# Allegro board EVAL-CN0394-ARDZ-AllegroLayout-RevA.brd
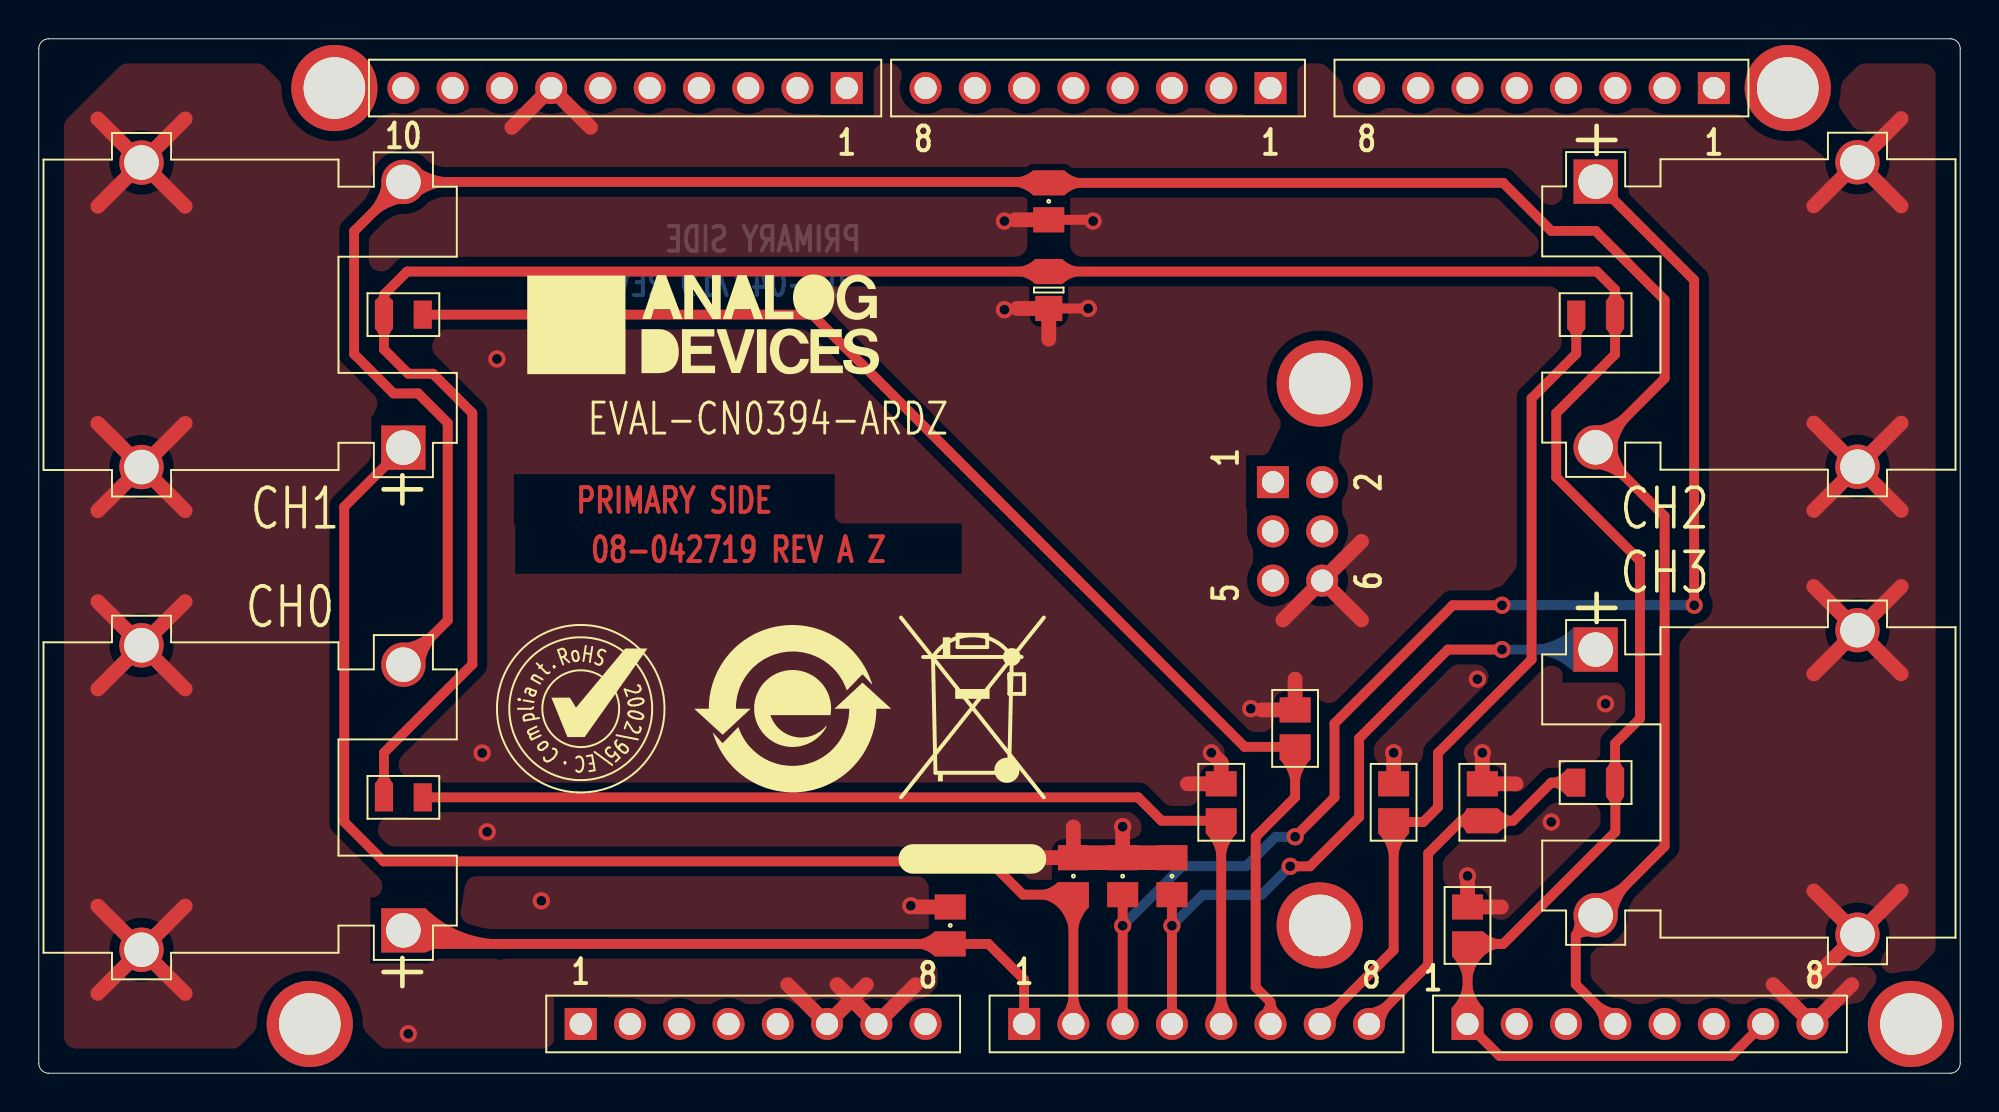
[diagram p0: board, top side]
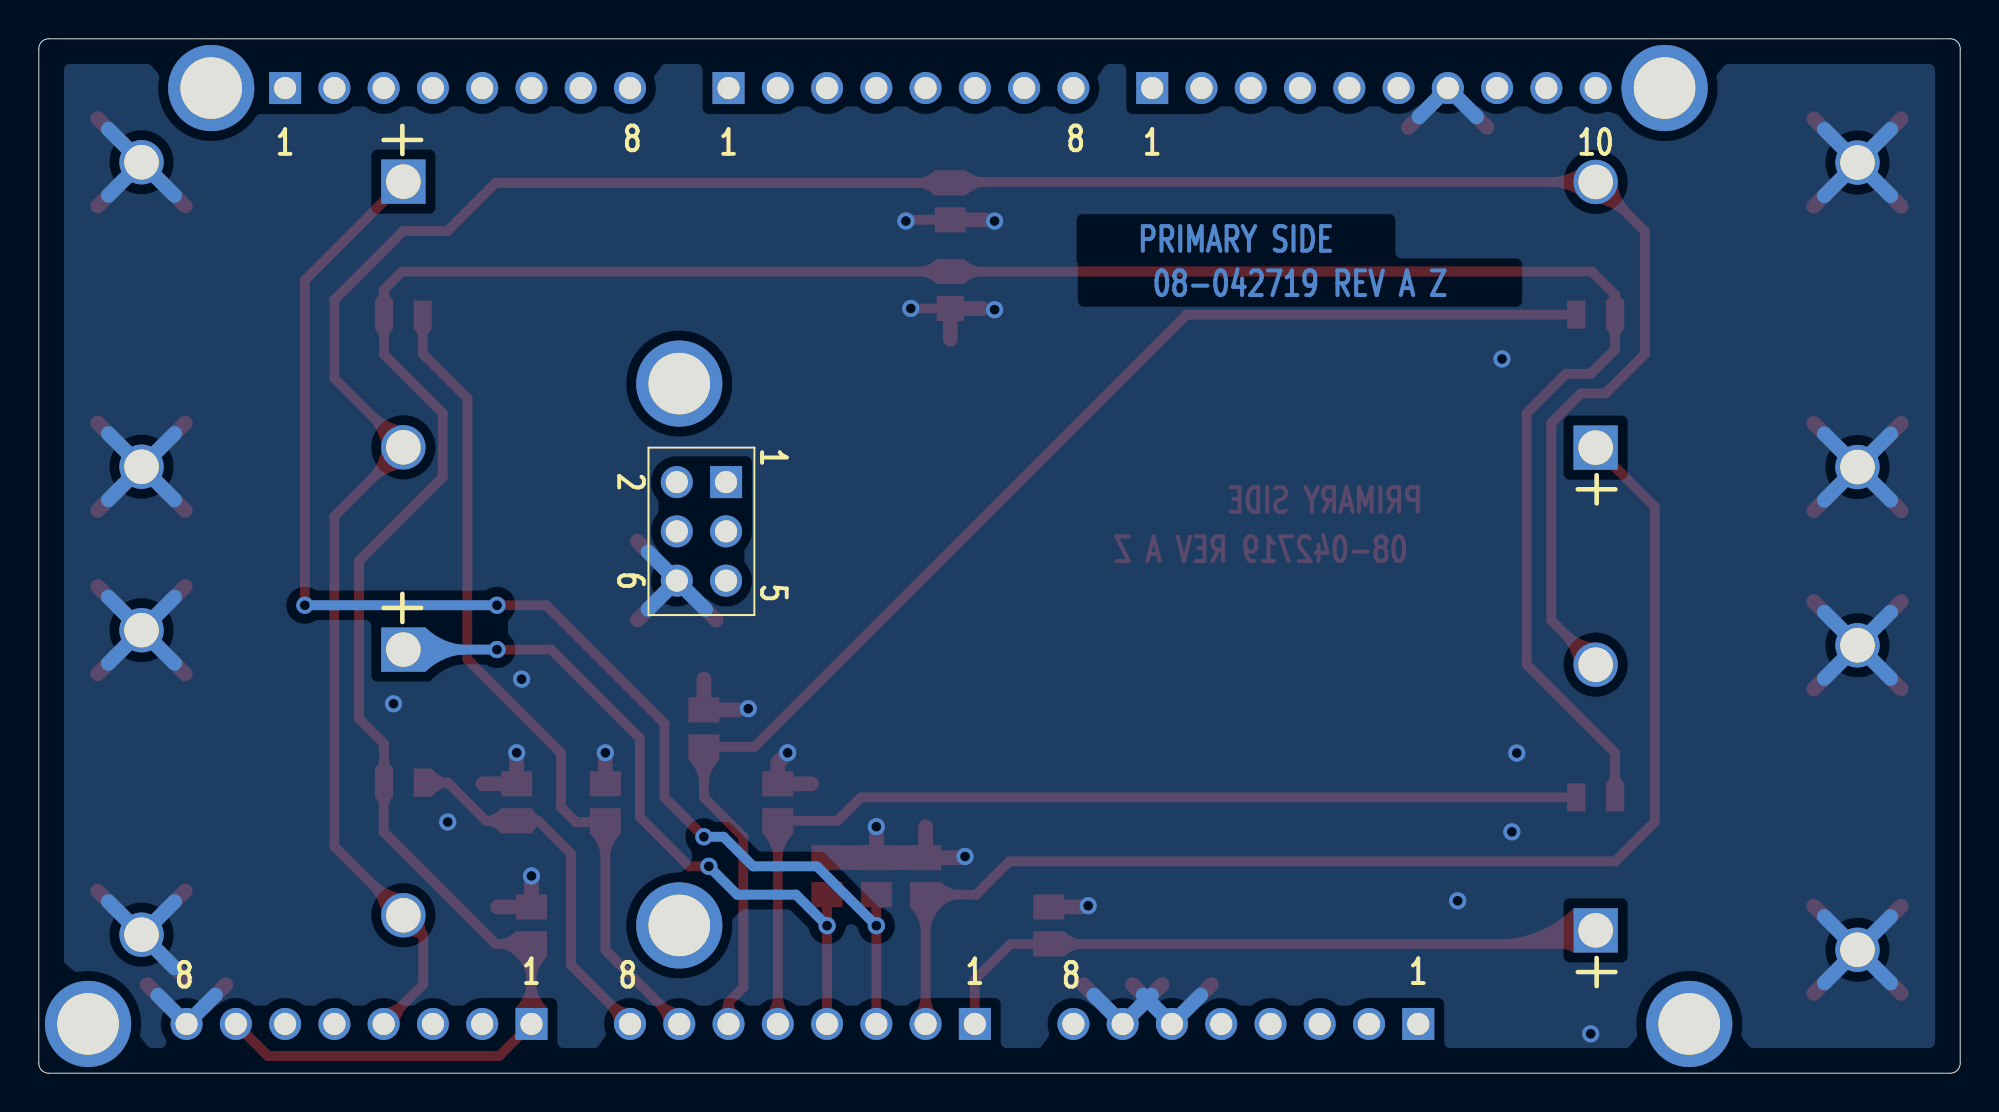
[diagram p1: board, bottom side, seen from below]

Outline 99.06 x 53.34 mm; copper layers: TOP, BOTTOM. Coordinates in mm from the lower left corner of the outline.
Outline path: 0,52.83 0,0.51 arc(0.15,0.15) 0.51,0 98.55,0 arc(98.91,0.15) 99.06,0.51 99.06,52.83 arc(98.91,53.19) 98.55,53.34 0.51,53.34 arc(0.15,53.19) 0,52.83

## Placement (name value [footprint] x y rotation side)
C1  0.47uF  [C0805]  46.99 7.62 90 top
C2  0.47uF  [C0805]  53.34 10.16 90 top
C3  0.47uF  [C0805]  55.88 10.16 90 top
C4  0.47uF  [C0805]  58.42 10.16 90 top
C5  0.47uF  [C0805]  52.07 44.96 270 top
C6  0.1uF  [C0805H53]  60.96 13.97 90 top
C7  0.1uF  [C0805H53]  64.77 17.78 90 top
C8  0.1uF  [C0805H53]  73.66 7.62 90 top
C9  0.1uF  [C0805H53]  69.85 13.97 90 top
C10  0.1uF  [C0805H53]  74.42 13.97 90 top
NOREF  -  []  38.86 18.8 0 top
NOREF#2  -  []  -25.4 275.59 0 top
NOREF#3  -  []  -92.71 -99.06 0 top
NOREF#4  -  [unnamed#2]  66.04 7.62 0 top
NOREF#5  -  []  -92.71 -99.06 0 top
NOREF#6  -  [unnamed#2]  13.97 2.54 0 top
NOREF#7  -  []  0.51 0 0 top
NOREF#8  -  []  0 0.51 0 top
NOREF#9  -  []  166.37 313.69 0 top
NOREF#10  -  []  13.97 2.54 0 top
NOREF#11  -  [unnamed#2]  90.17 50.8 0 top
NOREF#12  -  []  -92.71 -99.06 0 top
NOREF#13  -  []  99.06 0.51 0 top
NOREF#14  -  [unnamed#2]  96.52 2.54 0 top
NOREF#15  -  []  -1.27 44.45 0 top
NOREF#16  -  []  13.97 2.54 0 top
NOREF#17  -  []  57.4 27.18 0 top
NOREF#18  -  []  98.94 53.16 0 top
NOREF#19  -  []  97.64 0 90 top
NOREF#20  -  [unnamed#2]  15.24 50.8 0 top
NOREF#21  -  []  27.94 18.8 0 top
NOREF#22  -  [unnamed#2]  66.04 35.56 0 top
NOREF#23  -  []  0 52.83 0 top
NOREF#24  -  []  201.93 63.5 0 top
NOREF#25  -  []  34.75 37.31 0 top
NOREF#26  -  []  0.51 53.34 0 top
NOREF#27  -  []  13.98 55.24 180 bottom
P1  PCC-SMP-U-100-ROHS  [CNOMEGAPCC-SMP]  18.8 7.37 90 top
P2  PCC-SMP-U-100-ROHS  [CNOMEGAPCC-SMP]  18.8 32.26 90 top
P3  PCC-SMP-U-100-ROHS  [CNOMEGAPCC-SMP]  80.26 45.97 270 top
P4  PCC-SMP-U-100-ROHS  [CNOMEGAPCC-SMP]  80.26 21.84 270 top
P5  SSQ-108-03-G-S  [CNSAMTECSSQ-108-XX-X-S]  27.94 2.54 0 top
P6  SSQ-108-03-G-S  [CNSAMTECSSQ-108-XX-X-S]  50.8 2.54 0 top
P7  SSQ-108-03-G-S  [CNSAMTECSSQ-108-XX-X-S]  73.66 2.54 0 top
P8  SSQ-103-03-G-D  [CNSAMTECSSQ-103-XX-X-D]  63.63 30.48 270 bottom
P9  SSQ-110-03-G-S  [CNSAMTECSSQ-110-XX-X-S]  41.66 50.8 180 top
P10  SSQ-108-03-G-S  [CNSAMTECSSQ-108-XX-X-S]  63.5 50.8 180 top
P11  SSQ-108-03-G-S  [CNSAMTECSSQ-108-XX-X-S]  86.36 50.8 180 top
R1  1K  [R0805H20]  18.8 14.22 180 top
R2  1K  [R0805H20]  18.8 39.12 180 top
R3  1K  [R0805H20]  80.26 39.12 0 top
R4  1K  [R0805H20]  80.26 14.99 0 top
R5  1.6K  [R0805]  52.07 40.39 270 top

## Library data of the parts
C1-C5 = CAP: Tolerance: 10; User Part Number: UPN; part number: CAP_SM-0.47UF,16V,10,E000566,C0805; tolerance: 10
C6-C10 = CAP: Tolerance: 10; User Part Number: UPN; part number: CAP_SM-0.1UF,25V,10,E012855,C0805H53; tolerance: 10
P1-P4 = CN2P_2PSHLD: User Part Number: UPN; Tolerance: N/A; part number: CN2P_2PSHLD_TH-PCC-SMP-U-100-ROHS,E025050,CNOMEGAPCC-SMP; tolerance: N/A
P5-P7 P10 P11 = CN8P_A: User Part Number: UPN; Tolerance: N/A; part number: CN8P_A_TH-SSQ-108-03-G-S,E020478,CNSAMTECSSQ-108-XX-X-S; tolerance: N/A
P8 = CN6P: User Part Number: UPN; Tolerance: N/A; part number: CN6P_TH-SSQ-103-03-G-D,E020488,CNSAMTECSSQ-103-XX-X-D; tolerance: N/A
P9 = CN10P: User Part Number: UPN; Tolerance: N/A; part number: CN10P_TH-SSQ-110-03-G-S,E020479,CNSAMTECSSQ-110-XX-X-S; tolerance: N/A
R1-R4 = RES: Tolerance: 0.12; User Part Number: UPN; part number: RES_SM-1K,E025151,N/A,0.12,R0805H20; tolerance: 0.12
R5 = RES: Tolerance: 0.1; User Part Number: UPN; part number: RES_SM-1.6K,E003823,1/8W,0.1,R0805; tolerance: 0.1

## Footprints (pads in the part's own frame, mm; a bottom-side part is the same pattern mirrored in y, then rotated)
C0805
  rect 1.295x1.6 smd: 1(-0.953,0) 2(0.953,0)
C0805H53
  rect 1.295x1.6 smd: 1(-0.953,0) 2(0.953,0)
CNOMEGAPCC-SMP
  rect 2.286x2.286 hole 1.778: 1(0,0)
  round 2.286 hole 1.778: 2(13.7,0) SH1(-1,13.5) SH2(14.7,13.5)
CNSAMTECSSQ-103-XX-X-D
  rect 1.651x1.651 hole 1.143: 1(0,0)
  round 1.651 hole 1.143: 2(0,-2.54) 3(2.54,0) 4(2.54,-2.54) 5(5.08,0) 6(5.08,-2.54)
CNSAMTECSSQ-108-XX-X-S
  rect 1.651x1.651 hole 1.143: 1(0,0)
  round 1.651 hole 1.143: 2(2.54,0) 3(5.08,0) 4(7.62,0) 5(10.16,0) 6(12.7,0) 7(15.24,0) 8(17.78,0)
CNSAMTECSSQ-110-XX-X-S
  rect 1.651x1.651 hole 1.143: 1(0,0)
  round 1.651 hole 1.143: 2(2.54,0) 3(5.08,0) 4(7.62,0) 5(10.16,0) 6(12.7,0) 7(15.24,0) 8(17.78,0) 9(20.32,0) 10(22.86,0)
R0805
  rect 1.295x1.397 smd: 1(-0.953,0) 2(0.953,0)
R0805H20
  rect 0.94x1.448 smd: 1(-1,0) 2(1,0)
unnamed#2
  round 4.445 hole 3.175 unplated: (0,0)

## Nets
GND: C1.2(N2) C2.2(N2) C3.2(N2) C4.2(N2) C5.2(N2) C6.2(N2) C7.2(N2) C8.2(N2) C9.2(N2) C10.2(N2) P1.SH1 P1.SH2 P2.SH1 P2.SH2 P3.SH1 P3.SH2 P4.SH1 P4.SH2 P5.6(N6) P5.7(N7) P7.8(N8) P8.6(N6) P9.7(N7) R5.2(N2)
AIN0: C1.1(N1) P1.1(N1) P6.1(N1)
AIN1: C2.1(N1) P2.1(N1) P6.2(N2)
AIN2: C3.1(N1) P3.1(N1) P6.3(N3)
AIN3: C4.1(N1) P4.1(N1) P6.4(N4)
AIN4: C6.1(N1) P6.5(N5) R1.1(N1)
AIN5: C7.1(N1) P6.6(N6) R2.1(N1)
AIN6: C9.1(N1) P6.7(N7) R3.1(N1)
AIN7: C10.1(N1) P6.8(N8) R4.1(N1)
AIN11: C5.1(N1) P1.2(N2) P2.2(N2) P3.2(N2) P4.2(N2) P7.4(N4)
VREFP: C8.1(N1) P7.1(N1) P7.7(N7) R1.2(N2) R2.2(N2) R3.2(N2) R4.2(N2) R5.1(N1)

Pads without a net: P5 1 2 3 4 5 8; P7 2 3 5 6; P8 1 2 3 4 5; P9 1 2 3 4 5 6 8 9 10; P10 1 2 3 4 5 6 7 8; P11 1 2 3 4 5 6 7 8

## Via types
v1: diameter 0.889, hole 0.508, TOP to BOTTOM, 27 vias

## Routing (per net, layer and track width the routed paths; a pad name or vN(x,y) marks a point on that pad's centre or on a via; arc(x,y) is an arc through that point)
GND: length 259.3
  TOP w0.508: R5.2 v1(54.1,39.43) 54.29,39.43 ; 74.42,16.51 v1(74.42,16.52) ; 45.02,8.57 v1(44.96,8.64) ; C5.2 54.29,44.01 v1(54.36,43.94) ; v1(51.31,11.18) 51.37,11.11 ; 73.66,10.16 v1(73.66,10.17)
  TOP w0.762: 42.67,4.57 P5.6 38.61,4.57 ; 45.25,8.57 C1.2 ; 3.04,33.51 P2.SH1 ; P2.SH1 7.55,29.01 ; P2.SH1 7.55,33.51 ; P2.SH1 3.04,29.01 ; 91.51,20.59 P4.SH1 ; P4.SH1 96.02,20.59 ; P4.SH1 91.51,25.1 ; P4.SH1 96.02,25.1 ; P3.SH1 96.02,44.72 ; P3.SH1 91.51,44.72 ; P3.SH1 96.02,49.23 ; 59.22,14.92 C6.2 60.96,16.01 v1(60.45,16.52) ; 91.51,29.02 P3.SH2 ; P3.SH2 91.51,33.53 ; P3.SH2 96.02,29.02 ; P3.SH2 96.02,33.53 ; 93.47,4.57 P7.8 89.41,4.57 ; P1.SH1 7.55,4.11 ; P1.SH1 3.04,4.11 ; P1.SH1 3.04,8.62 ; P1.SH1 7.55,8.62 ; 76.16,14.92 C10.2 74.42,16.51 ; 41.15,4.57 P5.7 45.21,4.57 ; 3.04,44.71 P2.SH2 ; P2.SH2 3.04,49.21 ; P2.SH2 7.55,49.21 ; P2.SH2 7.55,44.71 ; 64.14,23.37 P8.6 ; P8.6 68.19,23.37 ; P8.6 68.19,27.43 ; C3.2 55.88,12.7 ; P4.SH2 96.02,9.4 ; P4.SH2 91.51,9.4 ; P4.SH2 91.51,4.89 ; 24.39,48.77 P9.7 28.44,48.77 ; 75.4,8.57 C8.2 73.66,10.16 ; 3.04,19.81 P1.SH2 ; P1.SH2 7.55,19.81 ; P1.SH2 3.04,24.32 ; P1.SH2 7.55,24.32 ; 63.03,18.73 C7.2 64.77,20.32 ; 51.6,11.11 C2.2 53.34,12.7 ; 52.07,37.85 R5.2 50.43,39.43 ; C9.2 69.85,16.51 ; 50.33,44.01 C5.2
  TOP w1.27: C4.2 C3.2 C2.2
  BOTTOM w0.762: P1.SH2 7.01,20.36 ; P1.SH2 3.59,23.78 ; P1.SH2 7.01,23.78 ; P1.SH2 3.59,20.36 ; P4.SH1 95.47,24.55 ; P4.SH1 92.05,24.55 ; P4.SH1 95.47,21.13 ; P4.SH1 92.05,21.13 ; 42.13,4.03 P5.6 39.15,4.03 ; 92.05,29.56 P3.SH2 ; P3.SH2 95.47,29.56 ; P3.SH2 95.47,32.98 ; P3.SH2 92.05,32.98 ; P3.SH1 95.47,48.68 ; P3.SH1 92.05,45.26 ; P3.SH1 95.47,45.26 ; 41.69,4.03 P5.7 44.67,4.03 ; 92.93,4.03 P7.8 89.95,4.03 ; P2.SH2 7.01,48.67 ; P2.SH2 3.59,48.67 ; P2.SH2 7.01,45.25 ; P2.SH2 3.59,45.25 ; P2.SH1 7.01,29.55 ; P2.SH1 3.59,29.55 ; P2.SH1 3.59,32.97 ; P2.SH1 7.01,32.97 ; 3.59,4.66 P1.SH1 ; P1.SH1 3.59,8.08 ; P1.SH1 7.01,8.08 ; P1.SH1 7.01,4.66 ; 64.68,23.91 P8.6 ; P8.6 67.65,23.91 ; P8.6 67.65,26.89 ; P4.SH2 95.47,8.85 ; P4.SH2 92.05,5.43 ; P4.SH2 92.05,8.85 ; 24.93,49.31 P9.7 27.9,49.31
  vias: v1(19.05,2.03) v1(22.86,16.51) v1(23.11,12.45) v1(23.62,36.83) v1(25.91,8.89) v1(49.78,43.94) v1(49.78,39.37) v1(55.88,12.71) v1(62.48,18.8) v1(69.85,16.52) v1(74.17,20.32) v1(77.98,12.95) v1(80.77,19.05)
AIN0: length 35.3
  TOP w0.508: P1.1 19.49,6.67 C1.1 48.96,6.67 50.8,4.83 P6.1
AIN1: length 66.4
  TOP w0.508: P6.2 C2.1 50.74,9.21 49.02,10.92 17.78,10.92 15.75,12.95 15.75,29.21 P2.1
AIN2: length 69.2
  TOP w0.508: v1(75.44,24.13) 72.9,24.13 66.8,18.03 66.8,14.22 v1(64.77,12.19) ; P6.3 v1(55.88,7.61) C3.1 ; P3.1 85.34,40.89 v1(85.34,24.13)
  BOTTOM w0.508: v1(55.88,7.61) 58.94,10.67 62.23,10.67 63.75,12.19 v1(64.77,12.19) ; v1(85.34,24.13) v1(75.44,24.13)
AIN3: length 36.8
  TOP w0.508: P6.4 v1(58.42,7.61) C4.1 ; v1(75.44,21.84) 72.64,21.84 68.07,17.27 68.07,13.21 65.53,10.67 v1(64.52,10.67)
  BOTTOM w0.508: v1(64.52,10.67) 63.06,9.21 60.02,9.21 v1(58.42,7.61) ; P4.1 v1(75.44,21.84)
AIN4: length 52.1
  TOP w0.508: R1.1 56.68,14.22 57.88,13.02 C6.1 P6.5
AIN5: length 69.7
  TOP w0.508: P6.6 63.5,3.67 62.74,4.43 62.74,12.19 64.77,14.22 C7.1 62.17,16.83 39.88,39.12 R2.1
AIN6: length 43
  TOP w0.508: P6.7 69.85,6.35 C9.1 69.91,12.95 71.37,12.95 72.14,13.72 72.14,16.51 76.96,21.34 76.96,34.8 79.26,37.1 R3.1
AIN7: length 19.2
  TOP w0.508: R4.1 77.98,14.99 76.01,13.02 C10.1 73.32,13.02 71.63,11.33 71.63,5.59 P6.8
AIN11: length 140.2
  TOP w0.508: P7.4 79.24,4.58 79.24,7.12 P4.2 83.82,11.7 83.82,28.72 P3.2 83.82,35.83 83.82,39.88 80.26,43.43 77.98,43.43 75.5,45.91 C5.1 52.02,45.96 P2.2 16.26,43.42 16.26,37.08 18.29,35.05 19.56,35.05 21.08,33.53 21.08,23.35 P1.2
VREFP: length 157.1
  TOP w0.508: P7.7 87.25,0.89 75.31,0.89 P7.1 C8.1 75.5,6.67 81.28,12.45 81.28,14.97 R4.2 81.26,17 82.55,18.29 82.55,26.42 78.23,30.73 78.23,34.04 81.26,37.07 R3.2 81.26,40.4 80.33,41.34 R5.1 18.99,41.34 17.8,40.14 R2.2 17.8,37.32 19.05,36.07 20.32,36.07 22.35,34.04 22.35,21.08 17.8,16.53 R1.2

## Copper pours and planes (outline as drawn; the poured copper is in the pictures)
GND on TOP: 1.3,1.27 1.3,49.05 4.32,52.07 97.79,52.07 97.79,1.27 72.47,1.27 72.47,5.11 69.24,5.11 69.24,1.27 49.78,1.27 49.78,3.17 50.42,3.17 50.42,4.19 53.09,4.19 53.09,8.89 50.29,8.89 50.29,10.03 48.01,10.03 48.01,7.11 49.78,7.11 49.78,5.84 46.35,5.84 46.35,3.81 45.85,3.81 45.85,1.27 ; 7 cut-outs
GND on BOTTOM: 1.3,1.3 1.3,52.04 97.76,52.04 97.76,1.3 ; 1 cut-out

Small or netless copper shapes (teardrops, artwork), in the pictures only: 38 on TOP, 1 on BOTTOM

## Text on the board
BOTTOM: 08-042719 REV A Z | PRIMARY SIDE
TOP: PRIMARY SIDE | 08-042719 REV A Z
Ref Des/Silkscreen Top: EVAL-CN0394-ARDZ | CH0 | CH1 | CH2 | CH3
DIMENSION: REF | x4 | DIA MAX
PAGE_OUTLINE: EVAL-CN0394-ARDZ | CUSTOMER EVAL BOARD Z
User.45: FIGURE | SIZE | 20.0 | 45.0 | 70.0 | 125.0 | PLATED | NON-PLATED | FINISHED HOLES IN MILS | ALL UNITS ARE IN MILS | QTY | 27 | 56 | 16 | 6 | TOLERANCE/NOTES
